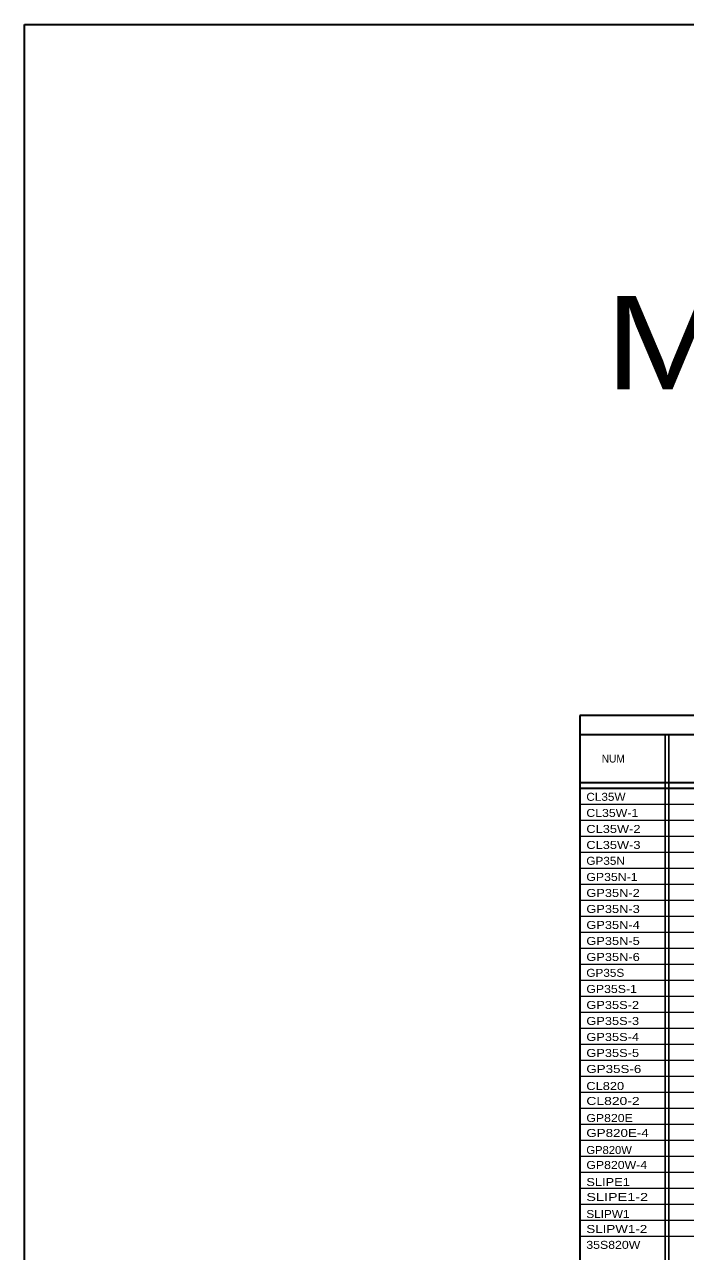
# Model space of a CAD drawing. Extents: x 1953053 to 1967065, y 7363860 to 7371201.
# Drawn here: x 1953053 to 1954045, y 7369361 to 7371201 of the extents above; entities that cross this region are included whole.
import ezdxf
from ezdxf.enums import TextEntityAlignment as Align

# ---------------------------------------------------------------- set-up
doc = ezdxf.new("R2010")
doc.units = 0
doc.header["$LTSCALE"] = 4.8
doc.layers.add('10', color=7, linetype='Continuous')
doc.layers.add('12', color=7, linetype='Continuous', lineweight=25)
doc.layers.add('62', color=7, linetype='Continuous', lineweight=35)

msp = doc.modelspace()

# ---------------------------------------------------------------- linework, layer by layer
at = {"layer": '12', "lineweight": 35}
for p, q in [((1955609.815, 7370164.879), (1953886.483, 7370164.879)), ((1953886.483, 7370164.879), (1953886.483, 7370055.746)), ((1953886.483, 7370136.079), (1955609.815, 7370136.079)), ((1953886.483, 7370064.079), (1955609.815, 7370064.079)), ((1953886.483, 7370055.746), (1955609.815, 7370055.746)), ((1953886.483, 7370055.746), (1953886.483, 7367775.748))]:
    msp.add_line(p, q, dxfattribs=at)
at = {"layer": '12'}
for p, q in [((1954014.328, 7370136.079), (1954014.328, 7369838.526)), ((1954014.328, 7370136.079), (1954014.328, 7367775.748)), ((1954019.815, 7370136.079), (1954019.815, 7367775.748))]:
    msp.add_line(p, q, dxfattribs=at)
at = {"layer": '12', "lineweight": 13}
for p, q in [((1953886.483, 7370031.746), (1955609.815, 7370031.746)), ((1953886.483, 7370007.746), (1955609.815, 7370007.746)), ((1953886.483, 7369983.746), (1955609.815, 7369983.746)), ((1953886.483, 7369959.746), (1955609.815, 7369959.746)), ((1953886.483, 7369935.746), (1955609.815, 7369935.746)), ((1953886.483, 7369911.746), (1955609.815, 7369911.746)), ((1953886.483, 7369887.746), (1955609.815, 7369887.746)), ((1953886.483, 7369887.746), (1955609.815, 7369887.746)), ((1953886.483, 7369863.746), (1955609.815, 7369863.746)), ((1953886.483, 7369839.746), (1955609.815, 7369839.746)), ((1953886.483, 7369815.746), (1955609.815, 7369815.746)), ((1953886.483, 7369791.746), (1955609.815, 7369791.746)), ((1953886.483, 7369767.746), (1955609.815, 7369767.746)), ((1953886.483, 7369743.746), (1955609.815, 7369743.746)), ((1953886.483, 7369719.746), (1955609.815, 7369719.746)), ((1953886.483, 7369695.746), (1955609.815, 7369695.746)), ((1953886.483, 7369671.746), (1955609.815, 7369671.746)), ((1953886.483, 7369647.746), (1955609.815, 7369647.746)), ((1953886.483, 7369623.746), (1955609.815, 7369623.746)), ((1953886.483, 7369599.746), (1955609.815, 7369599.746)), ((1953886.483, 7369575.746), (1955609.815, 7369575.746)), ((1953886.483, 7369551.746), (1954797.799, 7369551.746)), ((1953886.483, 7369527.748), (1955609.815, 7369527.748)), ((1953886.483, 7369503.748), (1955609.815, 7369503.748)), ((1953886.483, 7369479.748), (1955609.815, 7369479.748)), ((1953886.483, 7369455.748), (1955609.815, 7369455.748)), ((1953886.483, 7369431.748), (1955609.815, 7369431.748)), ((1953886.483, 7369407.748), (1955609.815, 7369407.748)), ((1953886.483, 7369383.748), (1955609.815, 7369383.748))]:
    msp.add_line(p, q, dxfattribs=at)
at = {"layer": '62'}
msp.add_lwpolyline([(1953052.784, 7371201.108), (1967065.314, 7371201.108), (1967065.314, 7363859.877), (1953052.784, 7363859.877)], close=True, dxfattribs=at)

# ---------------------------------------------------------------- texts
at = {"layer": '10'}
for s, width, p in [('CL35W', 1.1, (1953896.104, 7370036.747)), ('CL35W-1', 1.15, (1953896.104, 7370012.573)), ('CL35W-2', 1.2, (1953896.104, 7369988.573)), ('CL35W-3', 1.2, (1953896.104, 7369964.573)), ('GP35N', 1.1, (1953896.104, 7369940.747)), ('GP35N-1', 1.15, (1953896.104, 7369916.573)), ('GP35N-2', 1.2, (1953896.104, 7369892.573)), ('GP35N-3', 1.2, (1953896.104, 7369868.573)), ('GP35N-4', 1.2, (1953896.104, 7369844.573)), ('GP35N-5', 1.2, (1953896.104, 7369820.573)), ('GP35N-6', 1.2, (1953896.104, 7369796.573)), ('GP35S', 1.1, (1953896.104, 7369772.747)), ('GP35S-1', 1.15, (1953896.104, 7369748.573)), ('GP35S-2', 1.2, (1953896.104, 7369724.573)), ('GP35S-3', 1.2, (1953896.104, 7369700.573)), ('GP35S-4', 1.2, (1953896.104, 7369676.573)), ('GP35S-5', 1.2, (1953896.104, 7369652.573)), ('GP35S-6', 1.25, (1953896.104, 7369628.573)), ('CL820', 1.2, (1953896.104, 7369603.016)), ('CL820-2', 1.3, (1953896.104, 7369580.573)), ('GP820E', 1.15, (1953896.104, 7369555.018)), ('GP820E-4', 1.25, (1953896.104, 7369532.575)), ('GP820W', 1.05, (1953896.104, 7369507.018)), ('GP820W-4', 1.15, (1953896.104, 7369484.575)), ('SLIPE1', 1.2, (1953896.104, 7369459.018)), ('SLIPE1-2', 1.35, (1953896.104, 7369436.575)), ('SLIPW1', 1.1, (1953896.104, 7369411.018)), ('SLIPW1-2', 1.25, (1953896.104, 7369388.575)), ('35S820W', 1.15, (1953896.104, 7369364.741))]:
    msp.add_text(s, height=12, dxfattribs=dict(at, width=width)).set_placement(p)
at = {"layer": '12', "width": 0.95}
msp.add_text('NUM', height=12, dxfattribs=at).set_placement((1953936.529, 7370094.075), align=Align.CENTER)
at = {"layer": '62', "width": 1.2}
msp.add_text('MAINLANES & RAMPS', height=140, dxfattribs=at).set_placement((1955110.243, 7370654.085), align=Align.CENTER)

doc.saveas('drawing.dxf')
